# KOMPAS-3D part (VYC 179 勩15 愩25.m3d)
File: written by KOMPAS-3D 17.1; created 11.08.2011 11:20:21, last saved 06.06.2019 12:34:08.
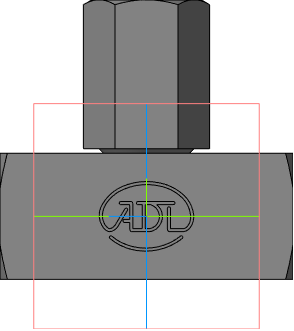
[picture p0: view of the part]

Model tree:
1. Плоскость XY
2. Плоскость ZX
3. Плоскость ZY
4. Ось X
5. Ось Y
6. Ось Z
7. Начало координат
8. Операция без истории:2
